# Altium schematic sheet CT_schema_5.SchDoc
size 284 x 147 mm
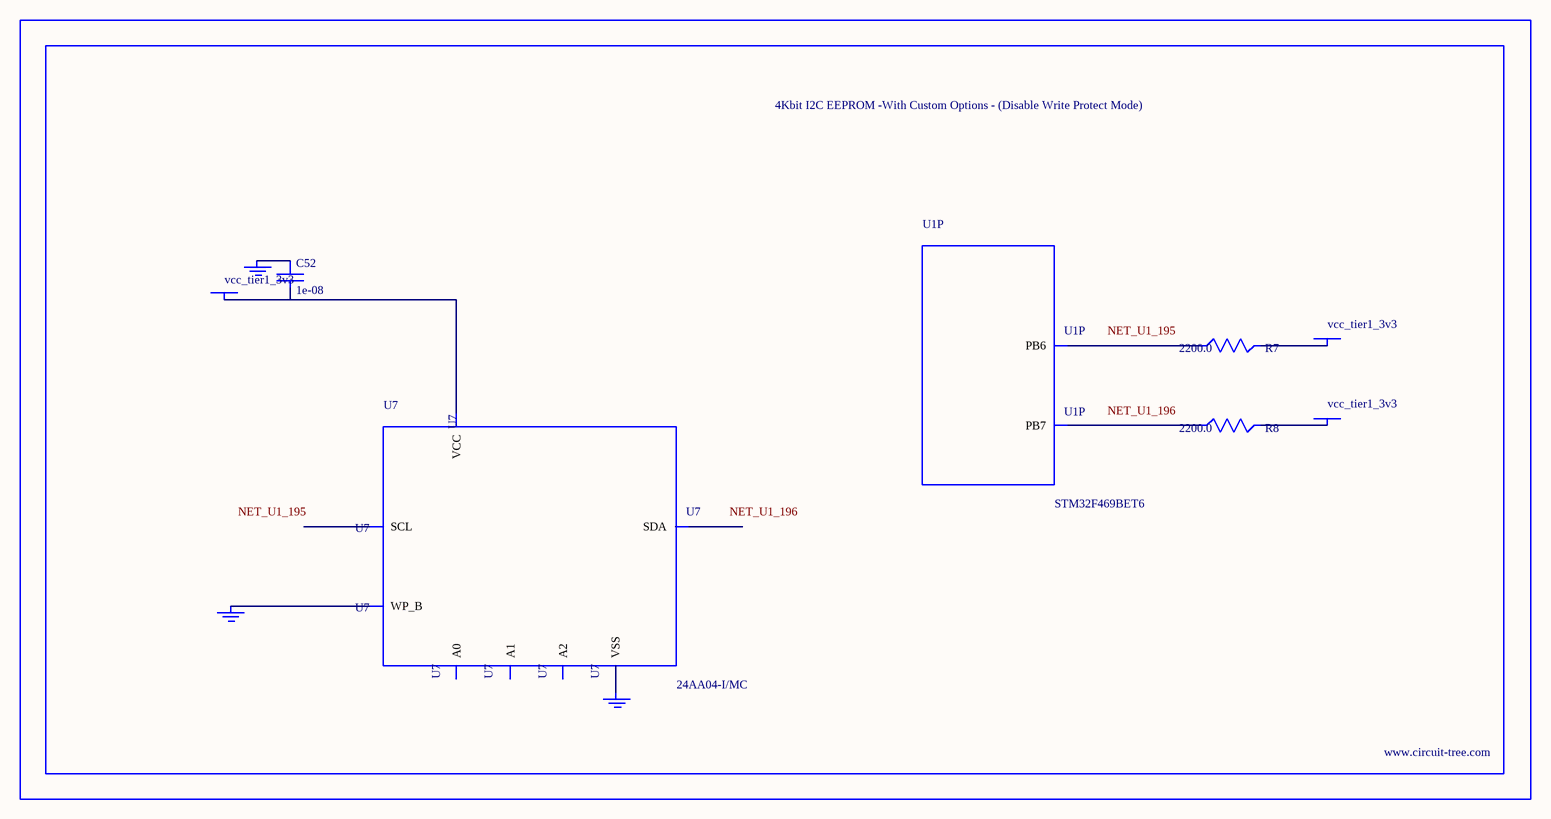
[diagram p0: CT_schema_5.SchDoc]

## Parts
BORDER4  (no value)
C52  1e-08  [C0402]
GND_INSTANCE_4_0  (no value)
GND_INSTANCE_4_1  (no value)
GND_INSTANCE_4_2  (no value)
POWER_INSTANCE_4_0  vcc_tier1_3v3
POWER_INSTANCE_4_1  vcc_tier1_3v3
POWER_INSTANCE_4_2  vcc_tier1_3v3
R7  2200.0  [R0603]
R8  2200.0  [R0603]
U1  STM32F469BET6  [LQFP208]  (part P of 18)
U7  24AA04-I/MC  [TDFN-8/6MM]

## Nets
NetC52_1: C52.1 GND_INSTANCE_4_1.0(GND)
NetC52_2: C52.2 POWER_INSTANCE_4_0.0(PWR) U7.8(VCC)
NetGND_INSTANCE_4_0_0: GND_INSTANCE_4_0.0(GND) U7.7(WP_B)
NetGND_INSTANCE_4_2_0: GND_INSTANCE_4_2.0(GND) U7.4(VSS)
NetPOWER_INSTANCE_4_1_0: POWER_INSTANCE_4_1.0(PWR) R7.2
NetPOWER_INSTANCE_4_2_0: POWER_INSTANCE_4_2.0(PWR) R8.2
NetR7_1: R7.1 U1.195(PB6)
NetR8_1: R8.1 U1.196(PB7)

Not connected (* = marked no-connect by the designer): U7 1(A0) 2(A1) 3(A2) 5(SDA) 6(SCL)

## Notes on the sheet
- Labels drawn without touching a wire or pin: NET_U1_195, NET_U1_196

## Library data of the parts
BORDER4 = BORDER_PAGE4
C52 = C0402C103K3RAC
GND_INSTANCE_4_0-GND_INSTANCE_4_2 = GND
POWER_INSTANCE_4_0-POWER_INSTANCE_4_2 = PWR
R7 R8 = RC0603JR-072K2L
